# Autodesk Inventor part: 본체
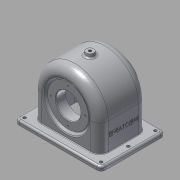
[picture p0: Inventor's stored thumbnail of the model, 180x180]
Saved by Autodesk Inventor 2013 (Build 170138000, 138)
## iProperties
Created: 2015-09
Part Number: 본체
Material: 알루미늄 6061
Document SubType Name: Modeling
Designer: dgall
Density: 2.71 g/cm^3
Mass: 671.534 g
Surface Area: 887.868 cm^2
Volume: 247.799 cm^3
Author: dgall
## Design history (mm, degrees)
sketch "스케치1"
  geometry: L1 (-70, 52)-(70, 52); L2 (70, 52)-(70, -52); L3 (70, -52)-(-70, -52); L4 (-70, -52)-(-70, 52); 1 further point
  constraints: 8 end point, 2 parallel, 1 horizontal, 1 perpendicular
  dimensions: "d1" = 140 distance of L2.end L3.end; "d3" = 104 distance of L1.end L2.end; "d4" = 52 distance from line of L1 point (0, 0); "d5" = 70 distance from line of L2 point (0, 0)
node "작업 평면1"
sketch "스케치2"
  geometry: L1 (0, 0)-(140, 0) reference; L2 (140, 7)-(0, 7) reference; L3 (16, 50.609)-(16, 7); L4 (124, 50.609)-(124, 7); A1 r 54 centre (70, 50.609) between (124, 50.609) and (16, 50.609); 1 further point
  constraints: 4 end point, 2 perpendicular, 2 point on circle, 2 point on line, 2 tangent, 1 centre point
  dimensions: "d14" = 0 horizontal distance of point (70, 0) A1.centre
extrude "돌출2" join sketch "스케치2" stored distance "d15" = 77; taper "d16" = 0 deg
feature "쉘1" dims "d17" = 5
fillet "모깎기1" dims "d20" = 14
sketch "스케치3"
  geometry: C1 r 31 at (70, -50.609); A1 r 40 centre (70, -50.609) between (30, -50.609) and (110, -50.609) reference; 1 further point
  constraints: 1 centre point, 1 coincident
  dimensions: "d21" = 62 diameter of C1
extrude "돌출4" join sketch "스케치3" distance "d23" = 10; taper "d24" = 0 deg
sketch "스케치4"
  geometry: C1 r 31 at (0, 0) reference; C2 r 20 at (0, 0); 1 further point
  constraints: 1 centre point, 1 coincident
  dimensions: "d25" = 40 diameter of C2
extrude "돌출5" cut sketch "스케치4" distance "d27" = 20; taper "d28" = 0 deg
node "작업 평면2"
sketch "스케치5"
  geometry: L1 (0, -14)-(-40, -14) reference; L2 (43.609, -14)-(0, -14) reference; L3 (0, -9)-(43.609, -9) reference; L4 (-49, -9)-(0, -9) reference; L5 (0, -14)-(0, 5); L6 (0, 5)-(-28, 5); L7 (-28, 5)-(-39.747, -9); L8 (-39.747, -9)-(0, -9); L9 (0, -9)-(0, 5); 1 further point
  constraints: 10 end point, 2 perpendicular, 1 collinear, 1 point on line
  dimensions: "d29" = 0 distance from line of L3.start L5; "d30" = 19 distance of L5.start L5.end; "d31" = 0 distance from line of L1 L5.start; "d32" = 50 deg angle of L6 L7; "d33" = 56 diameter of L6.end L5
revolve "회전1" sketch "스케치5" stored, may be unused: angle "d34" = 90 deg
sketch "스케치6"
  geometry: C1 r 28 at (0, 0) reference; C2 r 20 at (0, 0); 1 further point
  constraints: 1 centre point, 1 coincident
  dimensions: "d35" = 40 diameter of C2
extrude "돌출6" cut sketch "스케치6" distance "d37" = 16; taper "d38" = 0 deg
node "작업 평면3"
sketch "스케치7"
  geometry: L1 (-39.747, -9)-(-28, 5) reference; L2 (0, 0)-(0, -14) reference; L3 (0, -14)-(0, -14) reference; L4 (0, 0)-(0, -14) reference; L5 (0, 0)-(0, 0) reference; L6 (0, -14)-(-40, -14) reference; L7 (-33, -14)-(-33, -11); L8 (-33, -11)-(0, -11); 1 further point
  constraints: 4 end point, 2 perpendicular, 2 point on line
  dimensions: "d42" = 3 distance of L7.start L7.end; "d44" = 66 diameter of L7 L2
  node "투영된 루프1"
sketch "스케치8"
  geometry: C1 r 33 at (70, 50.609); A1 r 40 centre (70, 50.609) between (110, 50.609) and (30, 50.609) reference; 1 further point
  constraints: 1 centre point, 1 coincident
  dimensions: "d45" = 66 diameter of C1
extrude "돌출7" cut sketch "스케치8" distance "d47" = 3; taper "d48" = 0 deg
fillet "모깎기2" dims "d49" = 9
extrude "돌출8" join sketch "스케치1" distance "d50" = 7; taper "d51" = 0 deg
node "작업 평면4"
sketch "스케치9"
  geometry: L1 (0, -14)-(-40, -14) reference; L2 (-39.747, -9)-(-28, 5) reference; L3 (33, -14)-(-33, -14) reference; L4 (-20, -11)-(20, -11) reference; L5 (0, -14)-(0, 7.909); L6 (-37.416, -14)-(0, -14); L7 (-37.416, -14)-(-33, -8.737); L8 (33, -11)-(-33, -11) reference; L9 (-33, -11)-(-33, -8.737); L10 (-33, -11)-(0, -11); L11 (0, -14)-(0, -11); 1 further point
  constraints: 12 end point, 2 collinear, 1 midpoint, 1 parallel, 1 perpendicular, 1 point on line
  dimensions: "d53" = 5 distance between parallel lines of L2 L7
revolve "회전2" sketch "스케치9" stored, may be unused: angle "d54" = 90 deg
node "작업 평면5"
sketch "스케치10"
  geometry: L1 (-24.61, 34.544)-(24.61, 34.544); L2 (24.61, 34.544)-(24.61, 25.456); L3 (24.61, 25.456)-(-24.61, 25.456); L4 (-24.61, 25.456)-(-24.61, 34.544); L5 (-24.61, 30)-(24.61, 30); L6 (0, 34.544)-(0, 25.456); L7 (52, 0)-(-52, 0) reference; L8 (-38.5, 50.609)-(-38.5, 7) reference; 1 further point
  constraints: 4 end point, 4 midpoint, 2 other
  dimensions: "d56" = 30 distance between parallel lines of L7 L5; "d57" = 38.5 distance between parallel lines of L6 L8
feature "엠보싱1" sketch "스케치10" dims "d58" = 0.5, "d59" = 0
fillet "모깎기3" dims "d60" = 0.5
chamfer "모따기1" distance "d61" = 1; stored, may be unused: second distance "d62" = 2, angle "d63" = 45 deg
chamfer "모따기2" distance "d64" = 1; stored, may be unused: second distance "d65" = 2, angle "d66" = 45 deg
sketch "스케치11" dims "d67" = 56
  geometry: L1 (0, 0)-(0, 28); C1 r 21 at (0, 0) reference; 1 further point
  constraints: 2 end point, 1 coincident, 1 vertical, 1 vertical alignment, 2 other
hole "구멍1" sketch "스케치11" at (0, 28) diameter "d69" = 2.459; stored, may be unused: countersink angle "d73" = 90 deg, drill point angle "d75" = 118 deg; dims "d70" = 7, "d71" = 4, "d72" = 2, "d74" = 9
sketch "스케치12" dims "d79" = 48
  geometry: L1 (0, 0)-(0, -24); C1 r 21 at (0, 0) reference; 1 further point
  constraints: 2 end point, 1 coincident, 1 vertical, 1 vertical alignment, 2 other
hole "구멍2" sketch "스케치12" at (0, -24) diameter "d81" = 2.459; stored, may be unused: countersink angle "d85" = 90 deg, drill point angle "d87" = 118 deg; dims "d82" = 6, "d83" = 4, "d84" = 2, "d86" = 8
node "작업 평면6"
sketch "스케치13"
  geometry: C1 r 6 at (0, 0); 1 further point
  constraints: 1 centre point, 1 coincident
  dimensions: "d92" = 12 diameter of C1
extrude "돌출9" join sketch "스케치13" distance "d94" = 7; taper "d95" = 10 deg
fillet "모깎기4" dims "d96" = 3
fillet "모깎기5" dims "d97" = 7
fillet "모깎기6" dims "d98" = 3
fillet "모깎기7" dims "d99" = 1
sketch "스케치14"
  geometry: C1 r 6 at (0, 0) reference
hole "구멍3" sketch "스케치14" at (0, 0) diameter "d100" = 4.459; stored, may be unused: countersink angle "d104" = 90 deg, drill point angle "d106" = 118 deg; dims "d101" = 6, "d102" = 4, "d103" = 2, "d105" = 8
sketch "스케치15"
  geometry: L1 (-40, -33.5)-(40, -33.5) reference; L2 (49, -24.5)-(49, 24.5) reference; L3 (40, 33.5)-(-40, 33.5) reference; L4 (-49, 24.5)-(-49, -24.5) reference; A1 r 9 centre (-40, -24.5) between (-49, -24.5) and (-40, -33.5) reference; A2 r 9 centre (40, -24.5) between (40, -33.5) and (49, -24.5) reference; A3 r 9 centre (40, 24.5) between (49, 24.5) and (40, 33.5) reference; A4 r 9 centre (-40, 24.5) between (-40, 33.5) and (-49, 24.5) reference; 1 further point
extrude "돌출10" cut sketch "스케치15" stored distance "d107" = 10; taper "d108" = 0 deg
sketch "스케치16"
  geometry: L1 (63, 52)-(-63, 52) reference; L2 (-63, -52)-(63, -52) reference; L3 (-70, 45)-(-70, -45) reference; L4 (70, -45)-(70, 45) reference; C1 r 2.5 at (-62, 44); C2 r 2.5 at (-62, -44); C3 r 2.5 at (62, -44); C4 r 2.5 at (62, 44); C5 r 2.5 at (62, 0); C6 r 2.5 at (-62, 0); 1 further point
  constraints: 6 centre point
  dimensions: "d122" = 8 distance from line of L1 C4.centre; "d123" = 8 distance from line of L2 C3.centre; "d124" = 8 distance from line of L2 C2.centre; "d128" = 5 diameter of C1; "d129" = 5 diameter of C2; "d130" = 5 diameter of C3; "d131" = 5 diameter of C4; "d132" = 5 diameter of C5; "d133" = 5 diameter of C6; "d142" = 8 distance from line of L3 C2.centre; "d143" = 8 distance from line of C6.centre L3; "d144" = 8 distance from line of L3 C1.centre; "d145" = 8 distance from line of L4 C4.centre; "d146" = 8 distance from line of L4 C5.centre; "d147" = 8 distance from line of L4 C3.centre; "d148" = 44 distance of C3.centre C5.centre; "d149" = 44 distance of C2.centre C6.centre; "d150" = 44 distance of C6.centre C1.centre
extrude "돌출11" cut sketch "스케치16" stored distance "d134" = 10; taper "d135" = 0 deg
sketch "스케치17"
  geometry: C1 r 2.5 at (-62, 44) reference; C2 r 2.5 at (-30.624, 0); C3 r 2.5 at (-62, 0); 1 further point
  constraints: 2 centre point
  dimensions: "d138" = 44 distance of C1.centre C3.centre; "d139" = 5 diameter of C3
extrude "돌출12" cut sketch "스케치17" stored distance "d140" = 10; taper "d141" = 0 deg
fillet "모깎기8" dims "d151" = 3
node "솔리드1"
pattern_circular "원형 패턴1" dims angle "d77" = 360 deg
pattern_circular "원형 패턴2" dims angle "d89" = 360 deg
other parameters: "d13" = 108, "d55" = 81.25
